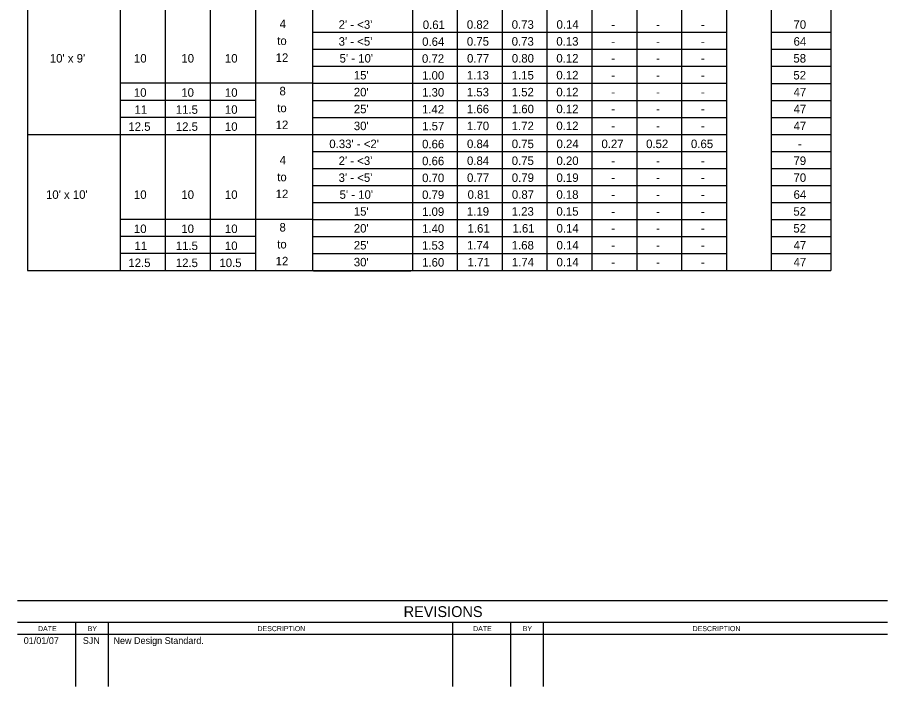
# Model space of a CAD drawing. Extents: x 10351.18 to 10353.4, y 76371.55 to 76372.62.
# Drawn here: x 10351.184 to 10351.829, y 76371.552 to 76372.047 of the extents above; entities that cross this region are included whole.
import ezdxf

# ---------------------------------------------------------------- set-up
doc = ezdxf.new("R2010")
doc.units = 0
for name, color, linetype in [('AdhocPoint_dp', 7, 'Continuous'), ('Border', 7, 'Continuous'), ('PlotBorder_dp', 7, 'Continuous')]:
    doc.layers.add(name, color=color, linetype=linetype)

msp = doc.modelspace()

# ---------------------------------------------------------------- linework, layer by layer
at = {"layer": 'Border'}
for p, q in [((10351.82859, 76371.61545), (10351.18448, 76371.61545)), ((10351.82859, 76371.59936), (10351.18448, 76371.59936)), ((10351.2275, 76371.59936), (10351.2275, 76371.55202)), ((10351.25167, 76371.59936), (10351.25167, 76371.55202)), ((10351.50654, 76371.59936), (10351.50654, 76371.55202)), ((10351.54956, 76371.59936), (10351.54956, 76371.55202)), ((10351.57373, 76371.59936), (10351.57373, 76371.55202)), ((10351.18448, 76371.59082), (10351.82859, 76371.59082))]:
    msp.add_line(p, q, dxfattribs=at)
at = {"layer": 'PlotBorder_dp'}
for p, q in [((10351.19191, 76372.53475), (10351.19191, 76371.85973)), ((10351.78665, 76372.53475), (10351.78665, 76371.85973)), ((10351.26055, 76372.51488), (10351.26055, 76371.85973)), ((10351.40299, 76372.51488), (10351.40299, 76371.85973)), ((10351.47687, 76372.51488), (10351.47687, 76371.85973)), ((10351.74246, 76372.51488), (10351.74246, 76371.85973)), ((10351.29391, 76372.50228), (10351.29391, 76371.85973)), ((10351.32727, 76372.50228), (10351.32727, 76371.85973)), ((10351.36063, 76372.50228), (10351.36063, 76371.85973)), ((10351.51007, 76372.47713), (10351.51007, 76371.85973)), ((10351.54327, 76372.47713), (10351.54327, 76371.85973)), ((10351.57647, 76372.47713), (10351.57647, 76371.85973)), ((10351.60967, 76372.47713), (10351.60967, 76371.85973)), ((10351.64287, 76372.47713), (10351.64287, 76371.85973)), ((10351.64287, 76372.47713), (10351.64287, 76371.85973)), ((10351.67606, 76372.47713), (10351.67606, 76371.85973)), ((10351.70926, 76372.47713), (10351.70926, 76371.85973)), ((10351.40299, 76372.03613), (10351.70926, 76372.03613)), ((10351.74246, 76372.03611), (10351.78665, 76372.03611)), ((10351.40299, 76372.02353), (10351.70926, 76372.02353)), ((10351.74246, 76372.02351), (10351.78665, 76372.02351)), ((10351.40299, 76372.01093), (10351.70926, 76372.01093)), ((10351.74246, 76372.01091), (10351.78665, 76372.01091)), ((10351.40299, 76371.99833), (10351.26055, 76371.99833)), ((10351.40299, 76371.99833), (10351.70926, 76371.99833)), ((10351.74246, 76371.99831), (10351.78665, 76371.99831)), ((10351.36063, 76371.98573), (10351.26055, 76371.98573)), ((10351.40299, 76371.98573), (10351.70926, 76371.98573)), ((10351.74246, 76371.98571), (10351.78665, 76371.98571)), ((10351.36063, 76371.97313), (10351.26055, 76371.97313)), ((10351.40299, 76371.97313), (10351.70926, 76371.97313)), ((10351.74246, 76371.97311), (10351.78665, 76371.97311)), ((10351.19191, 76371.96053), (10351.70926, 76371.96053)), ((10351.40362, 76371.96051), (10351.4758, 76371.96051)), ((10351.40362, 76371.96051), (10351.4758, 76371.96051)), ((10351.40362, 76371.96051), (10351.4758, 76371.96051)), ((10351.74246, 76371.96051), (10351.78665, 76371.96051)), ((10351.40299, 76371.94793), (10351.70926, 76371.94793)), ((10351.74246, 76371.94791), (10351.78665, 76371.94791)), ((10351.40299, 76371.93533), (10351.70926, 76371.93533)), ((10351.74246, 76371.93531), (10351.78665, 76371.93531)), ((10351.40299, 76371.92273), (10351.70926, 76371.92273)), ((10351.74246, 76371.92271), (10351.78665, 76371.92271)), ((10351.40299, 76371.91013), (10351.70926, 76371.91013)), ((10351.74246, 76371.91011), (10351.78665, 76371.91011)), ((10351.40299, 76371.89753), (10351.26055, 76371.89753)), ((10351.40299, 76371.89753), (10351.70926, 76371.89753)), ((10351.74246, 76371.89751), (10351.78665, 76371.89751)), ((10351.36063, 76371.88493), (10351.26055, 76371.88493)), ((10351.40299, 76371.88493), (10351.70926, 76371.88493)), ((10351.74246, 76371.88491), (10351.78665, 76371.88491)), ((10351.36063, 76371.87233), (10351.26055, 76371.87233)), ((10351.40299, 76371.87233), (10351.70926, 76371.87233)), ((10351.74246, 76371.87231), (10351.78665, 76371.87231)), ((10351.19191, 76371.85973), (10351.78665, 76371.85973)), ((10351.40362, 76371.85971), (10351.4758, 76371.85971)), ((10351.40362, 76371.85971), (10351.4758, 76371.85971)), ((10351.40362, 76371.85971), (10351.4758, 76371.85971)), ((10351.40362, 76371.85971), (10351.4758, 76371.85971))]:
    msp.add_line(p, q, dxfattribs=at)

# ---------------------------------------------------------------- texts
at = {"layer": 'AdhocPoint_dp'}
for s, height, p in [('10', 0.0063, (10351.27071, 76371.98838)), ('10', 0.0063, (10351.3058, 76371.98838)), ('10', 0.0063, (10351.33809, 76371.98838)), ('11', 0.0063, (10351.27123, 76371.97578)), ('11.5', 0.0063, (10351.3017, 76371.97578)), ('10', 0.0063, (10351.33809, 76371.97578)), ('12.5', 0.0063, (10351.26661, 76371.96318)), ('12.5', 0.0063, (10351.30171, 76371.96318)), ('10', 0.0063, (10351.33809, 76371.96318)), ('10', 0.0063, (10351.27071, 76371.88758)), ('10', 0.0063, (10351.3058, 76371.88758)), ('10', 0.0063, (10351.33809, 76371.88758)), ('11', 0.0063, (10351.27123, 76371.87498)), ('11.5', 0.0063, (10351.3017, 76371.87498)), ('10', 0.0063, (10351.33809, 76371.87498)), ('12.5', 0.0063, (10351.26661, 76371.86238)), ('12.5', 0.0063, (10351.30171, 76371.86238)), ('10.5', 0.0063, (10351.33399, 76371.86238)), ('REVISIONS', 0.008022, (10351.47037, 76371.60347)), ('BY', 0.003753, (10351.23648, 76371.59303)), ('BY', 0.003753, (10351.55855, 76371.59303)), ('01/01/07', 0.005, (10351.18915, 76371.58356)), ('SJN', 0.005, (10351.23288, 76371.58356)), ('New Design Standard.', 0.005, (10351.25558, 76371.58356))]:
    msp.add_text(s, height=height, dxfattribs=at).set_placement(p)
for s, height, rotation, p in [('DATE', 0.003737, 359.86925, (10351.19974, 76371.59305)), ('DESCRIPTION', 0.0037522, 0.04975, (10351.36218, 76371.59302)), ('DATE', 0.003737, 359.86925, (10351.52181, 76371.59305)), ('DESCRIPTION', 0.0037522, 0.04975, (10351.68424, 76371.59302))]:
    msp.add_text(s, height=height, rotation=rotation, dxfattribs=at).set_placement(p)
at = {"layer": 'PlotBorder_dp'}
for s, p in [('4', (10351.37857, 76372.03918)), ("2' - <3'", (10351.42225, 76372.03868)), ('0.61', (10351.48452, 76372.03852)), ('0.82', (10351.51715, 76372.03868)), ('0.73', (10351.55034, 76372.03868)), ('0.14', (10351.58352, 76372.03873)), ('70', (10351.75893, 76372.03868)), ('-', (10351.62403, 76372.03873)), ('-', (10351.65724, 76372.03873)), ('-', (10351.69043, 76372.03873)), ('to', (10351.37679, 76372.02668)), ("3' - <5'", (10351.42225, 76372.02618)), ('0.64', (10351.48407, 76372.02602)), ('0.75', (10351.51717, 76372.02618)), ('0.73', (10351.55034, 76372.02618)), ('0.13', (10351.58339, 76372.02623)), ('64', (10351.75898, 76372.02618)), ('-', (10351.62403, 76372.02623)), ('-', (10351.65724, 76372.02623)), ('-', (10351.69043, 76372.02623)), ("10' x 9'", (10351.20847, 76372.01368)), ('10', (10351.27075, 76372.01368)), ('10', (10351.30584, 76372.01368)), ('10', (10351.33808, 76372.01368)), ('12', (10351.37562, 76372.01418)), ("5' - 10'", (10351.42296, 76372.01368)), ('0.72', (10351.48395, 76372.01352)), ('0.77', (10351.51729, 76372.01368)), ('0.80', (10351.55043, 76372.01368)), ('0.12', (10351.5834, 76372.01373)), ('58', (10351.75887, 76372.01368)), ('-', (10351.62403, 76372.01373)), ('-', (10351.65724, 76372.01373)), ('-', (10351.69043, 76372.01373)), ("15'", (10351.43348, 76372.00118)), ('1.00', (10351.48403, 76372.00102)), ('1.13', (10351.51714, 76372.00118)), ('1.15', (10351.55037, 76372.00118)), ('0.12', (10351.5834, 76372.00123)), ('52', (10351.75885, 76372.00118)), ('-', (10351.62403, 76372.00123)), ('-', (10351.65724, 76372.00123)), ('-', (10351.69043, 76372.00123)), ('8', (10351.37846, 76371.98946)), ("20'", (10351.43348, 76371.98868)), ('1.30', (10351.48403, 76371.98852)), ('1.53', (10351.51714, 76371.98868)), ('1.52', (10351.55035, 76371.98868)), ('0.12', (10351.5834, 76371.98873)), ('47', (10351.759, 76371.98868)), ('-', (10351.62403, 76371.98873)), ('-', (10351.65724, 76371.98873)), ('-', (10351.69043, 76371.98873)), ('to', (10351.37679, 76371.97696)), ("25'", (10351.43348, 76371.97618)), ('1.42', (10351.48395, 76371.97602)), ('1.66', (10351.51721, 76371.97618)), ('1.60', (10351.55043, 76371.97618)), ('0.12', (10351.5834, 76371.97623)), ('-', (10351.62403, 76371.97623)), ('-', (10351.65724, 76371.97623)), ('-', (10351.69043, 76371.97623)), ('47', (10351.759, 76371.97618)), ('12', (10351.37562, 76371.96446)), ("30'", (10351.43348, 76371.96368)), ('1.57', (10351.48409, 76371.96352)), ('1.70', (10351.51722, 76371.96368)), ('1.72', (10351.55035, 76371.96368)), ('0.12', (10351.5834, 76371.96373)), ('-', (10351.62403, 76371.96373)), ('-', (10351.65724, 76371.96373)), ('-', (10351.69043, 76371.96373)), ('47', (10351.759, 76371.96368)), ("0.33' - <2'", (10351.41535, 76371.9504)), ('0.66', (10351.48401, 76371.95024)), ('0.84', (10351.51727, 76371.9504)), ('0.75', (10351.55037, 76371.9504)), ('0.24', (10351.58352, 76371.9504)), ('0.27', (10351.61677, 76371.9504)), ('0.52', (10351.64984, 76371.9504)), ('0.65', (10351.68305, 76371.9504)), ('-', (10351.76219, 76371.9504)), ('4', (10351.37857, 76371.93838)), ("2' - <3'", (10351.42225, 76371.9379)), ('0.66', (10351.48401, 76371.93774)), ('0.84', (10351.51727, 76371.9379)), ('0.75', (10351.55037, 76371.9379)), ('0.20', (10351.58348, 76371.9379)), ('-', (10351.62403, 76371.9379)), ('-', (10351.65724, 76371.9379)), ('-', (10351.69043, 76371.9379)), ('79', (10351.75892, 76371.9379)), ('to', (10351.37679, 76371.92588)), ("3' - <5'", (10351.42225, 76371.9254)), ('0.70', (10351.48403, 76371.92524)), ('0.77', (10351.51729, 76371.9254)), ('0.79', (10351.55041, 76371.9254)), ('0.19', (10351.58347, 76371.9254)), ('-', (10351.62403, 76371.9254)), ('-', (10351.65724, 76371.9254)), ('-', (10351.69043, 76371.9254)), ('70', (10351.75893, 76371.9254)), ("10' x 10'", (10351.20564, 76371.91285)), ('10', (10351.27075, 76371.91285)), ('10', (10351.30584, 76371.91285)), ('10', (10351.33808, 76371.91285)), ('12', (10351.37562, 76371.91338)), ("5' - 10'", (10351.42296, 76371.9129)), ('0.79', (10351.48401, 76371.91274)), ('0.81', (10351.51771, 76371.9129)), ('0.87', (10351.55049, 76371.9129)), ('0.18', (10351.58342, 76371.9129)), ('-', (10351.62403, 76371.9129)), ('-', (10351.65724, 76371.9129)), ('-', (10351.69043, 76371.9129)), ('64', (10351.75898, 76371.9129)), ("15'", (10351.43348, 76371.9004)), ('1.09', (10351.48401, 76371.90024)), ('1.19', (10351.51721, 76371.9004)), ('1.23', (10351.55034, 76371.9004)), ('0.15', (10351.58343, 76371.9004)), ('-', (10351.62403, 76371.9004)), ('-', (10351.65724, 76371.9004)), ('-', (10351.69043, 76371.9004)), ('52', (10351.75885, 76371.9004)), ('8', (10351.37846, 76371.88866)), ("20'", (10351.43348, 76371.8879)), ('1.40', (10351.48403, 76371.88774)), ('1.61', (10351.51771, 76371.8879)), ('1.61', (10351.55091, 76371.8879)), ('0.14', (10351.58352, 76371.8879)), ('-', (10351.62403, 76371.8879)), ('-', (10351.65724, 76371.8879)), ('-', (10351.69043, 76371.8879)), ('52', (10351.75885, 76371.8879)), ('to', (10351.37679, 76371.87616)), ("25'", (10351.43348, 76371.8754)), ('1.53', (10351.48394, 76371.87524)), ('1.74', (10351.51727, 76371.8754)), ('1.68', (10351.55037, 76371.8754)), ('0.14', (10351.58352, 76371.8754)), ('-', (10351.62403, 76371.8754)), ('-', (10351.65724, 76371.8754)), ('-', (10351.69043, 76371.8754)), ('47', (10351.759, 76371.8754)), ('12', (10351.37562, 76371.86366)), ("30'", (10351.43348, 76371.8629)), ('0.14', (10351.58352, 76371.8629)), ('1.60', (10351.48403, 76371.86274)), ('1.71', (10351.51771, 76371.8629)), ('1.74', (10351.55047, 76371.8629)), ('-', (10351.62403, 76371.8629)), ('-', (10351.65724, 76371.8629)), ('-', (10351.69043, 76371.8629)), ('47', (10351.759, 76371.8629))]:
    msp.add_text(s, height=0.0063, dxfattribs=at).set_placement(p)

doc.saveas('drawing.dxf')
